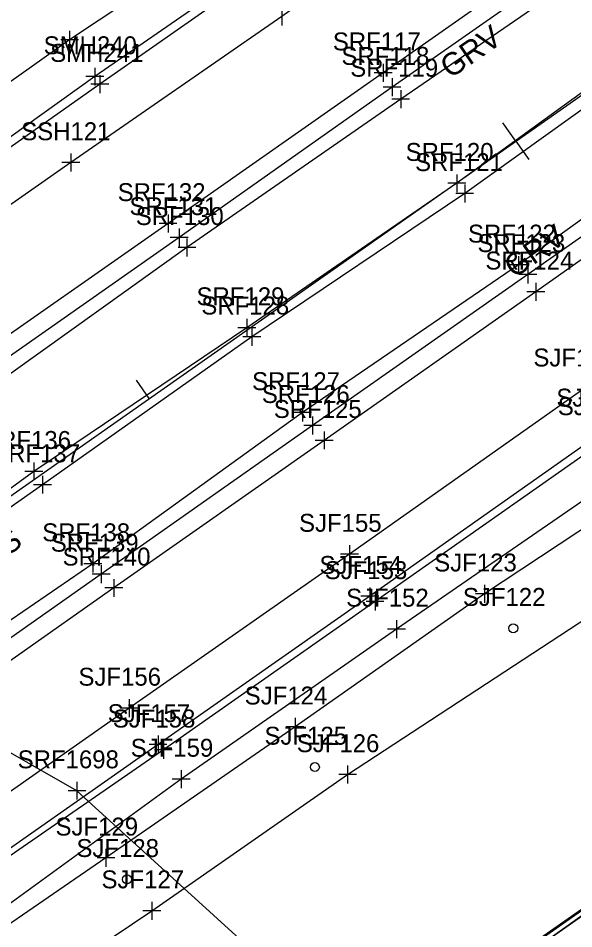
# Model space of a CAD drawing. Extents: x 941041 to 969446, y 397014 to 416764.
# Drawn here: x 953693.2 to 953817.3, y 404429.6 to 404632.9 of the extents above; entities that cross this region are included whole.
import ezdxf

# ---------------------------------------------------------------- set-up
doc = ezdxf.new("R2010")
doc.units = 0
for name, color, linetype in [('SURVEY - CENTERLINE - Preliminary', 7, 'Continuous'), ('SURVEY - CENTERLINE - Preliminary Curve Text', 7, 'Continuous'), ('SURVEY - DRAINAGE - Area Shapes', 7, 'Continuous'), ('SURVEY - DRAINAGE - Area Shapes - Points - Locators', 7, 'Continuous'), ('SURVEY - DRAINAGE - Area Shapes - Points - Numbers', 7, 'Continuous'), ('SURVEY - DTM - Breaklines', 7, 'Continuous'), ('SURVEY - DTM - Breaklines - Points - Locators', 7, 'Continuous'), ('SURVEY - DTM - Breaklines - Points - Numbers', 7, 'Continuous'), ('SURVEY - DTM - Spot Points - Locators', 7, 'Continuous'), ('SURVEY - DTM - Spot Points - Point Numbers', 7, 'Continuous'), ('SURVEY - DTM GRAPHICS - Boundary Line', 7, 'Continuous'), ('SURVEY - NON-TRANSPORTATION - Features', 7, 'Continuous'), ('SURVEY - PROPERTY - ROW Lines', 7, 'Continuous'), ('SURVEY - TRANSPORTATION - Features', 7, 'Continuous'), ('SURVEY - TRANSPORTATION - Features - Points - Locators', 7, 'Continuous'), ('SURVEY - TRANSPORTATION - Features - Points - Numbers', 7, 'Continuous'), ('SURVEY - TRANSPORTATION - Features Text', 7, 'Continuous'), ('SURVEY - TRANSPORTATION - Roads', 7, 'Continuous'), ('SURVEY - TRANSPORTATION - Roads - Points - Locators', 7, 'Continuous'), ('SURVEY - TRANSPORTATION - Roads - Points - Numbers', 7, 'Continuous'), ('SURVEY - VEGETATION - Features - Points - Locators', 7, 'Continuous'), ('SURVEY - VEGETATION - Features - Points - Numbers', 7, 'Continuous'), ('SURVEY - VEGETATION - Features with Text', 7, 'Continuous')]:
    doc.layers.add(name, color=color, linetype=linetype)

msp = doc.modelspace()

# ---------------------------------------------------------------- linework, layer by layer
at = {"layer": 'SURVEY - CENTERLINE - Preliminary'}
msp.add_line((950966.25, 402614.81), (953884.31, 404661.52), dxfattribs=at)
msp.add_line((950966.25, 402614.81), (953884.31, 404661.52), dxfattribs=at)
msp.add_line((950966.25, 402614.81), (953884.31, 404661.52), dxfattribs=at)
at = {"layer": 'SURVEY - CENTERLINE - Preliminary Curve Text'}
for p, q in [((953804.36, 404605.44), (953801.49, 404609.54)), ((953804.36, 404605.44), (953807.23, 404601.35)), ((953722.49, 404548.02), (953719.62, 404552.11))]:
    msp.add_line(p, q, dxfattribs=at)
at = {"layer": 'SURVEY - DRAINAGE - Area Shapes'}
msp.add_lwpolyline([(954050.98, 404130.56), (953837.45, 404341.16), (953706.36, 404460.47), (953686.21, 404471.93), (953450.22, 404306.36), (952524.78, 403657.05)], dxfattribs=at)
at = {"layer": 'SURVEY - DRAINAGE - Area Shapes - Points - Locators'}
for p, q in [((953706.36, 404462.47), (953706.36, 404458.47)), ((953706.36, 404462.47), (953706.36, 404458.47)), ((953708.36, 404460.47), (953704.36, 404460.47)), ((953708.36, 404460.47), (953704.36, 404460.47))]:
    msp.add_line(p, q, dxfattribs=at)
at = {"layer": 'SURVEY - DTM - Breaklines'}
for points in [[(953844.91, 404724.43), (953801.08, 404696), (953757.23, 404662.97), (953704.72, 404628.1), (953660.43, 404596.65), (953620.67, 404568.71), (953586.65, 404544.2), (953541.12, 404517.43), (953497.56, 404486.63), (953444.55, 404448.74), (953398.22, 404415.52), (953345.9, 404378.38), (953294.56, 404341.68), (953245.65, 404308.78), (953189.47, 404270.12), (953139.94, 404234.41), (953096.09, 404203.86), (953048.64, 404170.72), (953010.5, 404143.31), (952970.47, 404114.09), (952926.3, 404087.24)], [(953883.69, 404663.04), (953839.24, 404630.89), (953791.17, 404596.04), (953744.31, 404563.82), (953696.75, 404531.75), (953651.72, 404498.86), (953606.38, 404468.15), (953556.11, 404434.09), (953507.9, 404400.44), (953458.58, 404365.63), (953409.93, 404330.34)], [(953885.68, 404660.84), (953840.72, 404627.95), (953792.94, 404593.77), (953745.42, 404561.76), (953698.67, 404528.77), (953653.27, 404496.86), (953608.47, 404466.02), (953557.75, 404431.71), (953509.03, 404398.54), (953460.14, 404363.38), (953411.39, 404328.38)], [(953923.28, 404599.55), (953876.94, 404567.21), (953829.38, 404532.12), (953777.71, 404496.55), (953729.61, 404463.05), (953677.11, 404424.98), (953628.97, 404392.23), (953593.9, 404365.72), (953577.48, 404348.57), (953495.56, 404253.05)], [(953930.5, 404594.79), (953899.28, 404573.09), (953853.92, 404543.05), (953843.46, 404534.82), (953797.38, 404504.4), (953755.05, 404474.71), (953712.83, 404445.46), (953669.81, 404415.98), (953611.07, 404372.77), (953586.59, 404349.95), (953558.91, 404313.55), (953497.8, 404249.13), (953473.51, 404228.83), (953446.86, 404209.01), (953450.01, 404200.36), (953460.86, 404196.95), (953466.73, 404189.97)]]:
    msp.add_lwpolyline(points, dxfattribs=at)
at = {"layer": 'SURVEY - DTM - Breaklines - Points - Locators'}
for p, q in [((953704.72, 404630.1), (953704.72, 404626.1)), ((953706.72, 404628.1), (953702.72, 404628.1)), ((953791.17, 404598.04), (953791.17, 404594.04)), ((953793.17, 404596.04), (953789.17, 404596.04)), ((953792.94, 404595.77), (953792.94, 404591.77)), ((953794.94, 404593.77), (953790.94, 404593.77)), ((953746.31, 404563.82), (953742.31, 404563.82)), ((953744.31, 404565.82), (953744.31, 404561.82)), ((953745.42, 404563.76), (953745.42, 404559.76)), ((953747.42, 404561.76), (953743.42, 404561.76)), ((953696.75, 404533.75), (953696.75, 404529.75)), ((953698.75, 404531.75), (953694.75, 404531.75)), ((953698.67, 404530.77), (953698.67, 404526.77)), ((953700.67, 404528.77), (953696.67, 404528.77)), ((953797.38, 404506.4), (953797.38, 404502.4)), ((953799.38, 404504.4), (953795.38, 404504.4)), ((953777.71, 404498.55), (953777.71, 404494.55)), ((953779.71, 404496.55), (953775.71, 404496.55)), ((953755.05, 404476.71), (953755.05, 404472.71)), ((953757.05, 404474.71), (953753.05, 404474.71)), ((953729.61, 404465.05), (953729.61, 404461.05)), ((953731.61, 404463.05), (953727.61, 404463.05)), ((953712.83, 404447.46), (953712.83, 404443.46)), ((953714.83, 404445.46), (953710.83, 404445.46))]:
    msp.add_line(p, q, dxfattribs=at)
at = {"layer": 'SURVEY - DTM - Spot Points - Locators'}
for centre in [(953803.78, 404496.72), (953759.48, 404465.74), (953717.53, 404440.67)]:
    msp.add_circle(centre, 1, dxfattribs=at)
at = {"layer": 'SURVEY - DTM GRAPHICS - Boundary Line'}
msp.add_lwpolyline([(953513.57, 404220.43), (953655.88, 404319.66), (953696.45, 404348.27), (953787.18, 404409.93), (953933.92, 404514.34), (953978, 404545.36), (953953.37, 404554.61), (953940, 404588.29), (953930.5, 404594.79), (953923.28, 404599.55), (953918.44, 404605.51), (953917.37, 404606.65), (953912.33, 404615.61), (953902.72, 404637.94)], dxfattribs=at)
at = {"layer": 'SURVEY - NON-TRANSPORTATION - Features'}
msp.add_lwpolyline([(953978, 404545.36), (953933.92, 404514.34), (953696.45, 404348.27), (953696.45, 404348.27), (953655.88, 404319.66), (953513.57, 404220.43), (953466.74, 404188.39)], dxfattribs=at)
at = {"layer": 'SURVEY - PROPERTY - ROW Lines'}
msp.add_line((952368.92, 403415.42), (953970.44, 404538.71), dxfattribs=at)
at = {"layer": 'SURVEY - TRANSPORTATION - Features'}
for points in [[(953850.15, 404717.97), (953807.34, 404688.26), (953761.74, 404655.35), (953710.33, 404619.85), (953664.48, 404587.1), (953626.26, 404560.43), (953592.18, 404536.69), (953549.02, 404506.45), (953505.37, 404475.88), (953451.57, 404438.49), (953405.14, 404405.66), (953352.63, 404368.46), (953300.5, 404332.24), (953251.5, 404297.73), (953196.36, 404259.29), (953147.01, 404224.16), (953103.25, 404193.85), (953055.57, 404160.17), (953016.57, 404133.76), (952975.96, 404105.95), (952933.14, 404076.27)], [(953869.92, 404678.92), (953827.09, 404648.11), (953778.65, 404614.84), (953730.92, 404581.73), (953684.94, 404548.88), (953639.42, 404515.85), (953592.65, 404484.5), (953544.29, 404450.02), (953496.96, 404418.25), (953446.56, 404382.28), (953397.21, 404347.28), (953349.09, 404313.97), (953306.79, 404283.35), (953259.52, 404249.57), (953215.62, 404219), (953162.75, 404182.43), (953116.47, 404149.89), (953065.89, 404114.72), (953020.62, 404083), (952970.12, 404047.84), (952922.32, 404014.23)], [(953898.36, 404644.24), (953852.94, 404612.35), (953804.92, 404577.81), (953756.7, 404544.88), (953709.89, 404511.14), (953665.52, 404480.77), (953619.89, 404448.73), (953571.72, 404414.34), (953522.34, 404379.83), (953473.43, 404345.59), (953425.03, 404311.48), (953376.74, 404277.44), (953331.82, 404246.3), (953285.64, 404214.9), (953239.25, 404182.51), (953188.82, 404146.7), (953139.07, 404111.93), (953091.16, 404078.74), (953044.12, 404045.63), (952994.26, 404010.63)], [(953918.44, 404605.51), (953871.93, 404572.47), (953825.16, 404539.29), (953772.92, 404502.69), (953725.65, 404469.57), (953671.12, 404431.98), (953624.16, 404398.66), (953570.35, 404360.17), (953529.67, 404332.52), (953477.08, 404295.12), (953452.64, 404278.33), (953404.53, 404245.13), (953366.78, 404218.04)]]:
    msp.add_lwpolyline(points, dxfattribs=at)
at = {"layer": 'SURVEY - TRANSPORTATION - Features - Points - Locators'}
for p, q in [((953710.33, 404621.85), (953710.33, 404617.85)), ((953712.33, 404619.85), (953708.33, 404619.85)), ((953778.65, 404616.84), (953778.65, 404612.84)), ((953780.65, 404614.84), (953776.65, 404614.84)), ((953730.92, 404583.73), (953730.92, 404579.73)), ((953732.92, 404581.73), (953728.92, 404581.73)), ((953804.92, 404579.81), (953804.92, 404575.81)), ((953806.92, 404577.81), (953802.92, 404577.81)), ((953756.7, 404546.88), (953756.7, 404542.88)), ((953758.7, 404544.88), (953754.7, 404544.88)), ((953709.89, 404513.14), (953709.89, 404509.14)), ((953711.89, 404511.14), (953707.89, 404511.14)), ((953772.92, 404504.69), (953772.92, 404500.69)), ((953774.92, 404502.69), (953770.92, 404502.69)), ((953725.65, 404471.57), (953725.65, 404467.57)), ((953727.65, 404469.57), (953723.65, 404469.57))]:
    msp.add_line(p, q, dxfattribs=at)
at = {"layer": 'SURVEY - TRANSPORTATION - Roads'}
for points in [[(953851.13, 404715.85), (953808.94, 404686.44), (953761.75, 404653.36), (953711.46, 404618.15), (953665.02, 404585.47), (953627.01, 404559.02), (953592.91, 404535.17), (953549.7, 404505.05), (953506.3, 404474.53), (953452.44, 404436.82), (953405.98, 404404.16), (953353.26, 404366.99), (953301.59, 404330.73), (953252.56, 404296.26), (953197.23, 404257.57), (953147.78, 404222.91), (953103.99, 404192.35), (953056.56, 404159.12), (953017.98, 404132.4), (952976.96, 404104.46), (952934.03, 404074.71)], [(953854.31, 404705.09), (953803.66, 404669.9), (953752.1, 404633.3), (953704.99, 404600.66), (953647.26, 404560.28), (953593.35, 404522.18), (953538.64, 404483.8), (953481.57, 404443.82), (953428.95, 404406.84), (953375.39, 404369.37), (953319.63, 404330.36), (953264.54, 404291.54), (953207.01, 404251.04), (953151.83, 404212.71), (953097.91, 404174.93), (953044.02, 404137.15), (952991.3, 404100.41), (952936.63, 404064.07), (952879.17, 404027.52), (952819.51, 403989.75), (952762.74, 403954.2), (952705, 403918.02), (952645.15, 403881.65), (952578.99, 403846.21)], [(953866.36, 404684.94), (953822.96, 404654.52), (953774.73, 404620.71), (953726.69, 404587.07), (953680.28, 404554.63), (953635.03, 404522.94), (953588.28, 404490.13), (953540.23, 404456.3), (953493.36, 404423.46), (953443.17, 404388.28), (953392.7, 404352.87), (953346.73, 404320.68), (953301.84, 404289.22), (953256, 404257.12), (953211.45, 404225.77), (953159.51, 404189.39), (953111.96, 404156.14), (953062.13, 404121.15), (953015.79, 404088.66), (952966.99, 404054.39), (952917.91, 404020.1)], [(953868, 404681.53), (953825.14, 404651.33), (953776.71, 404617.48), (953729.17, 404583.94), (953682.71, 404551.47), (953636.98, 404519.3), (953590.64, 404486.86), (953542.3, 404452.97), (953495.29, 404420.17), (953445.21, 404384.8), (953395.13, 404349.76), (953347.57, 404316.35), (953304.31, 404286), (953257.68, 404253.33), (953213.42, 404222.46), (953160.97, 404185.55), (953114.2, 404152.81), (953064.1, 404117.58), (953018.19, 404085.4), (952968.52, 404050.78), (952920.2, 404016.82)], [(953900.62, 404641.5), (953855.22, 404609.45), (953807.02, 404575.69), (953758.99, 404542.01), (953711.75, 404508.82), (953668.09, 404478.06), (953621.84, 404445.43), (953573.82, 404411.95), (953523.8, 404377.02), (953475.53, 404343.33), (953426.53, 404308.93), (953378.51, 404275.3), (953333.58, 404243.9), (953288.55, 404212.21), (953241.33, 404178.78), (953191.41, 404143.85), (953140.87, 404108.55), (953093.94, 404075.57), (953046.11, 404041.98), (952997.22, 404007.75)], [(953902.72, 404637.94), (953857.45, 404606.12), (953808.81, 404571.8), (953761.55, 404538.67), (953714.57, 404505.72), (953670.63, 404474.8), (953623.35, 404441.74), (953576.1, 404408.57), (953525.65, 404373.27), (953477.92, 404339.82), (953428.19, 404304.98), (953380.75, 404271.81), (953335.05, 404239.73), (953288.64, 404207.14), (953242.9, 404175.1), (953193.89, 404141.01), (953142.58, 404104.93), (953096.45, 404072.54), (953047.38, 404038.13), (952999.67, 404004.66)], [(953912.33, 404615.61), (953865.26, 404582.3), (953819.57, 404550.16), (953767.19, 404513.26), (953718.04, 404478.91), (953664.43, 404441.32), (953617.26, 404408.04), (953563.31, 404370.48), (953522.75, 404341.92), (953471.46, 404306.09), (953445.64, 404287.99), (953397.8, 404254.2), (953360.06, 404227.77)], [(953917.37, 404606.65), (953870.42, 404573.23), (953824.67, 404541.2), (953771.76, 404503.86), (953724.46, 404470.77), (953670.22, 404432.73), (953623.39, 404399.95), (953569.03, 404361.75), (953528.76, 404333.61), (953476.11, 404296.68), (953450.98, 404278.84), (953404.05, 404246.19), (953365.7, 404219.13)]]:
    msp.add_lwpolyline(points, dxfattribs=at)
at = {"layer": 'SURVEY - TRANSPORTATION - Roads - Points - Locators'}
for p, q in [((953752.1, 404635.3), (953752.1, 404631.3)), ((953776.73, 404620.71), (953772.73, 404620.71)), ((953774.73, 404622.71), (953774.73, 404618.71)), ((953711.46, 404620.15), (953711.46, 404616.15)), ((953776.71, 404619.48), (953776.71, 404615.48)), ((953713.46, 404618.15), (953709.46, 404618.15)), ((953778.71, 404617.48), (953774.71, 404617.48)), ((953704.99, 404602.66), (953704.99, 404598.66)), ((953706.99, 404600.66), (953702.99, 404600.66)), ((953726.69, 404589.07), (953726.69, 404585.07)), ((953728.69, 404587.07), (953724.69, 404587.07)), ((953729.17, 404585.94), (953729.17, 404581.94)), ((953731.17, 404583.94), (953727.17, 404583.94)), ((953807.02, 404577.69), (953807.02, 404573.69)), ((953809.02, 404575.69), (953805.02, 404575.69)), ((953808.81, 404573.8), (953808.81, 404569.8)), ((953810.81, 404571.8), (953806.81, 404571.8)), ((953758.99, 404544.01), (953758.99, 404540.01)), ((953760.99, 404542.01), (953756.99, 404542.01)), ((953761.55, 404540.67), (953761.55, 404536.67)), ((953763.55, 404538.67), (953759.55, 404538.67)), ((953767.19, 404515.26), (953767.19, 404511.26)), ((953769.19, 404513.26), (953765.19, 404513.26)), ((953711.75, 404510.82), (953711.75, 404506.82)), ((953713.75, 404508.82), (953709.75, 404508.82)), ((953714.57, 404507.72), (953714.57, 404503.72)), ((953716.57, 404505.72), (953712.57, 404505.72)), ((953771.76, 404505.86), (953771.76, 404501.86)), ((953773.76, 404503.86), (953769.76, 404503.86)), ((953718.04, 404480.91), (953718.04, 404476.91)), ((953720.04, 404478.91), (953716.04, 404478.91)), ((953724.46, 404472.77), (953724.46, 404468.77)), ((953726.46, 404470.77), (953722.46, 404470.77))]:
    msp.add_line(p, q, dxfattribs=at)
at = {"layer": 'SURVEY - VEGETATION - Features - Points - Locators'}
for p, q in [((953766.8, 404466.07), (953766.8, 404462.07)), ((953768.8, 404464.07), (953764.8, 404464.07)), ((953723.08, 404435.68), (953723.08, 404431.68)), ((953725.08, 404433.68), (953721.08, 404433.68))]:
    msp.add_line(p, q, dxfattribs=at)
at = {"layer": 'SURVEY - VEGETATION - Features with Text'}
for points in [[(953493.95, 404269.02), (953619.99, 404362.71), (953670.1, 404398.06), (953723.08, 404433.68), (953766.8, 404464.07), (953851.45, 404519.5), (953865.64, 404528.02), (953910.6, 404557.74), (953935, 404570.53)], [(953978, 404545.36), (952376.77, 403420.76)]]:
    msp.add_lwpolyline(points, dxfattribs=at)

# ---------------------------------------------------------------- texts
at = {"layer": 'SURVEY - DRAINAGE - Area Shapes - Points - Numbers'}
msp.add_text('SRF1698', height=4, dxfattribs=at).set_placement((953693.12, 404465.47))
msp.add_text('SRF1698', height=4, dxfattribs=at).set_placement((953693.12, 404465.47))
at = {"layer": 'SURVEY - DTM - Breaklines - Points - Numbers'}
for s, p in [('SRF120', (953779.76, 404601.04)), ('SRF121', (953781.86, 404598.77)), ('SRF129', (953733.06, 404568.82)), ('SRF128', (953734.13, 404566.76)), ('SRF136', (953685.4, 404536.75)), ('SRF137', (953687.43, 404533.77)), ('SJF123', (953786.14, 404509.4)), ('SJF152', (953766.47, 404501.55)), ('SJF124', (953743.81, 404479.71)), ('SJF159', (953718.36, 404468.05)), ('SJF129', (953701.57, 404450.46))]:
    msp.add_text(s, height=4, dxfattribs=at).set_placement(p)
at = {"layer": 'SURVEY - DTM - Spot Points - Point Numbers'}
for s, p in [('SJF122', (953792.54, 404501.72)), ('SJF125', (953748.24, 404470.74)), ('SJF128', (953706.24, 404445.67))]:
    msp.add_text(s, height=4, dxfattribs=at).set_placement(p)
at = {"layer": 'SURVEY - TRANSPORTATION - Features - Points - Numbers'}
for s, p in [('SMH240', (953698.92, 404624.85)), ('SRF119', (953767.39, 404619.84)), ('SRF130', (953719.5, 404586.73)), ('SRF122', (953793.68, 404582.81)), ('SRF127', (953745.46, 404549.88)), ('SJF150', (953813.75, 404544.29)), ('SRF138', (953698.6, 404516.14)), ('SJF153', (953761.68, 404507.69)), ('SJF158', (953714.36, 404474.57))]:
    msp.add_text(s, height=4, dxfattribs=at).set_placement(p)
at = {"layer": 'SURVEY - TRANSPORTATION - Features Text'}
for rotation, p in [(34.6027, (953789.71, 404619.29)), (35.0958, (953804.02, 404574.73))]:
    msp.add_text('GRV', height=5, rotation=rotation, dxfattribs=at).set_placement(p)
at = {"layer": 'SURVEY - TRANSPORTATION - Roads - Points - Numbers'}
for s, p in [('SRF117', (953763.5, 404625.71)), ('SMH241', (953700.38, 404623.15)), ('SRF118', (953765.42, 404622.48)), ('SSH121', (953693.91, 404605.66)), ('SRF132', (953715.45, 404592.07)), ('SRF131', (953718.09, 404588.94)), ('SRF123', (953795.78, 404580.69)), ('SRF124', (953797.57, 404576.8)), ('SJF148', (953808.29, 404555.16)), ('SRF126', (953747.64, 404547.01)), ('SJF149', (953813.41, 404546.2)), ('SRF125', (953750.31, 404543.67)), ('SJF155', (953755.95, 404518.26)), ('SRF139', (953700.5, 404513.82)), ('SRF140', (953703.15, 404510.72)), ('SJF154', (953760.52, 404508.86)), ('SJF156', (953706.69, 404483.91)), ('SJF157', (953713.22, 404475.77))]:
    msp.add_text(s, height=4, dxfattribs=at).set_placement(p)
at = {"layer": 'SURVEY - VEGETATION - Features - Points - Numbers'}
for s, p in [('SJF126', (953755.45, 404469.07)), ('SJF127', (953711.84, 404438.68))]:
    msp.add_text(s, height=4, dxfattribs=at).set_placement(p)
at = {"layer": 'SURVEY - VEGETATION - Features with Text'}
msp.add_text('GRASS', height=4.998, rotation=33.7585, dxfattribs=at).set_placement((953675.09, 404502.28))

doc.saveas('drawing.dxf')
